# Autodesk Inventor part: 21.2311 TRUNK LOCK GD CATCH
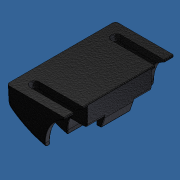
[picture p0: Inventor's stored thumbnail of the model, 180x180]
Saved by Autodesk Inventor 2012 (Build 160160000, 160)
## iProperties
Created: 2014-09
Part Number: 21.2311 TRUNK LOCK GD CATCH
Material: Aluminum-6061
Document SubType Name: Modeling
Designer: Admin
Density: 2.71 g/cm^3
Mass: 107.066 g
Surface Area: 110.888 cm^2
Volume: 39.5076 cm^3
Author: Admin
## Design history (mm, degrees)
feature "Base1"
body "Solid1"
